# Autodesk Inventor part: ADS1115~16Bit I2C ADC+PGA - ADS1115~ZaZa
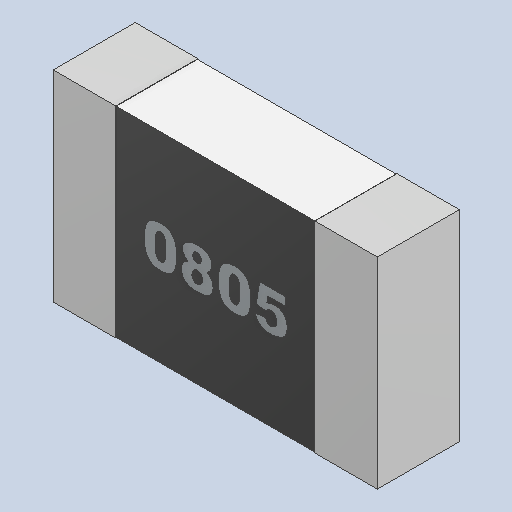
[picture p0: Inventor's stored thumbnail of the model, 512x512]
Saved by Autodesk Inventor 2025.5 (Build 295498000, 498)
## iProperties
Created: 2026-10
Part Number: ADS1115~16Bit I2C ADC+PGA - ADS1115~ZaZa
Material: Genérico
Description: 0805 Resistor
Document SubType Name: Modeling
Designer: Luis M
Density: 1 g/cm^3
Appearance: Valor por defecto
Author: Luis M
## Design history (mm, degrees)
feature "Base1"
node "Sólido1"
